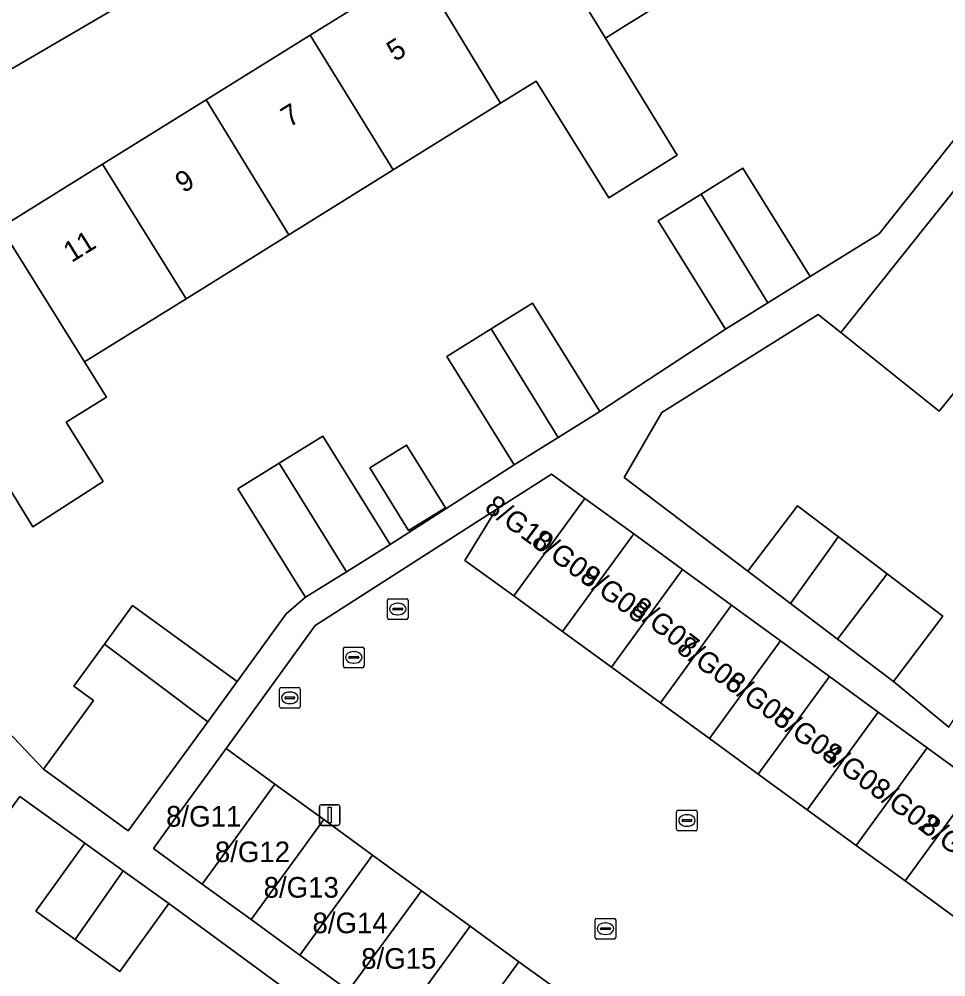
# Model space of a CAD drawing. Extents: x 159674 to 160531, y 382172 to 382904.
# Drawn here: x 160238.74 to 160283.66, y 382664.64 to 382711.06 of the extents above; entities that cross this region are included whole.
import ezdxf

# ---------------------------------------------------------------- set-up
doc = ezdxf.new("R2010")
doc.units = 0
for name, color, linetype in [('IMGEO_Erf', 7, 'Continuous'), ('IMGEO_Kolk', 7, 'Continuous'), ('IMGEO_Lichtmast', 7, 'Continuous'), ('IMGEO_Pand', 7, 'Continuous'), ('IMGEO_Pand_nummerreeks', 7, 'Continuous'), ('IMGEO_Rijbaan_lokaal_open', 7, 'Continuous'), ('IMGEO_Rioolput', 7, 'Continuous'), ('IMGEO_Voetpad_open', 7, 'Continuous')]:
    doc.layers.add(name, color=color, linetype=linetype)

msp = doc.modelspace()

# ---------------------------------------------------------------- linework, layer by layer
at = {"layer": 'IMGEO_Erf'}
for points in [[(160263.63, 382697.299), (160266.891, 382692.05), (160272.972, 382696.028), (160269.707, 382701.284), (160271.793, 382702.58), (160273.825, 382703.842), (160277.09, 382698.586), (160280.422, 382700.656), (160288.011, 382710.171), (160267.842, 382726.279), (160267.481, 382726.359), (160260.898, 382722.304), (160245.542, 382712.846), (160232.632, 382705.313), (160223.268, 382700.381)], [(160237.854, 382700.968), (160242.783, 382704.03), (160247.804, 382707.149), (160252.846, 382710.282), (160258.092, 382713.54), (160263.149, 382716.682), (160268.281, 382719.87), (160272.331, 382713.35), (160268.084, 382710.712), (160267.16, 382710.138), (160270.635, 382704.465), (160267.317, 382702.401), (160263.802, 382708.052), (160262.075, 382706.979), (160256.874, 382703.748), (160251.809, 382700.602), (160246.834, 382697.511), (160241.905, 382694.449), (160242.971, 382692.734), (160241.022, 382691.523), (160242.806, 382688.652), (160239.401, 382686.46), (160237.89, 382688.94)], [(160220.353, 382695.284), (160229.296, 382685.901), (160239.918, 382674.707), (160242.34, 382678.033), (160241.388, 382678.726), (160242.872, 382680.764), (160244.241, 382682.644), (160249.304, 382678.957), (160251.69, 382682.234), (160252.614, 382683.042), (160252.357, 382683.456), (160249.341, 382688.292), (160251.34, 382689.533), (160253.463, 382690.852), (160256.728, 382685.597), (160262.73, 382689.465), (160259.469, 382694.714), (160261.62, 382696.05), (160263.63, 382697.299)], [(160251.52, 382664.137), (160245.989, 382668.201), (160243.616, 382664.9), (160241.448, 382666.459), (160239.549, 382667.824), (160241.922, 382671.125), (160238.771, 382673.39), (160232.124, 382664.262)]]:
    msp.add_lwpolyline(points, dxfattribs=at)
for points in [[(160295.415, 382687.898), (160290.71, 382691.655), (160286.035, 382695.389), (160283.335, 382692.062), (160278.571, 382695.866), (160277.467, 382696.748), (160269.889, 382691.992), (160268.069, 382688.847), (160274.061, 382684.308), (160276.462, 382687.478), (160278.456, 382685.968), (160280.815, 382684.181), (160283.52, 382682.132), (160281.118, 382678.962), (160283.801, 382676.741), (160286.155, 382680.338), (160288.175, 382678.867), (160290.216, 382677.381), (160289.667, 382676.626), (160293.592, 382673.768), (160299.053, 382681.203), (160298.359, 382681.809), (160293.534, 382685.524)], [(160259.398, 382687.377), (160257.617, 382686.27), (160255.73, 382689.308), (160257.511, 382690.415)]]:
    msp.add_lwpolyline(points, close=True, dxfattribs=at)
at = {"layer": 'IMGEO_Kolk'}
for p, q in [((160256.591, 382682.042), (160256.591, 382682.894)), ((160256.666, 382682.968), (160257.518, 382682.968)), ((160257.079, 382682.748), (160257.104, 382682.748)), ((160257.592, 382682.894), (160257.592, 382682.042)), ((160256.85, 382682.462), (160256.85, 382682.474)), ((160257.288, 382682.425), (160256.89, 382682.425)), ((160256.893, 382682.511), (160257.291, 382682.511)), ((160257.102, 382682.188), (160257.077, 382682.188)), ((160257.334, 382682.474), (160257.334, 382682.462)), ((160257.518, 382681.968), (160256.666, 382681.968)), ((160251.361, 382677.74), (160251.361, 382678.592)), ((160251.436, 382678.666), (160252.288, 382678.666)), ((160252.362, 382678.592), (160252.362, 382677.74)), ((160251.62, 382678.16), (160251.62, 382678.172)), ((160252.058, 382678.123), (160251.66, 382678.123)), ((160251.663, 382678.209), (160252.061, 382678.209)), ((160251.849, 382678.446), (160251.874, 382678.446)), ((160252.104, 382678.172), (160252.104, 382678.16)), ((160252.288, 382677.666), (160251.436, 382677.666)), ((160251.872, 382677.886), (160251.847, 382677.886)), ((160270.611, 382671.796), (160270.611, 382672.648)), ((160270.686, 382672.722), (160271.538, 382672.722)), ((160271.099, 382672.502), (160271.124, 382672.502)), ((160271.612, 382672.648), (160271.612, 382671.796)), ((160270.87, 382672.216), (160270.87, 382672.228)), ((160271.308, 382672.179), (160270.91, 382672.179)), ((160270.913, 382672.265), (160271.311, 382672.265)), ((160271.354, 382672.228), (160271.354, 382672.216)), ((160271.538, 382671.722), (160270.686, 382671.722)), ((160271.122, 382671.942), (160271.097, 382671.942)), ((160266.659, 382666.55), (160266.659, 382667.402)), ((160266.734, 382667.476), (160267.586, 382667.476)), ((160267.66, 382667.402), (160267.66, 382666.55)), ((160266.918, 382666.97), (160266.918, 382666.982)), ((160267.356, 382666.933), (160266.958, 382666.933)), ((160266.961, 382667.019), (160267.359, 382667.019)), ((160267.147, 382667.256), (160267.172, 382667.256)), ((160267.402, 382666.982), (160267.402, 382666.97)), ((160267.586, 382666.476), (160266.734, 382666.476)), ((160267.17, 382666.696), (160267.145, 382666.696))]:
    msp.add_line(p, q, dxfattribs=at)
for points in [[(160256.591, 382682.042), (160256.591, 382682.894)], [(160256.666, 382682.968), (160257.518, 382682.968)], [(160257.592, 382682.894), (160257.592, 382682.042)], [(160257.518, 382681.968), (160256.666, 382681.968)], [(160251.361, 382677.74), (160251.361, 382678.592)], [(160251.436, 382678.666), (160252.288, 382678.666)], [(160252.362, 382678.592), (160252.362, 382677.74)], [(160252.288, 382677.666), (160251.436, 382677.666)], [(160270.611, 382671.796), (160270.611, 382672.648)], [(160270.686, 382672.722), (160271.538, 382672.722)], [(160271.612, 382672.648), (160271.612, 382671.796)], [(160271.538, 382671.722), (160270.686, 382671.722)], [(160266.659, 382666.55), (160266.659, 382667.402)], [(160266.734, 382667.476), (160267.586, 382667.476)], [(160267.66, 382667.402), (160267.66, 382666.55)], [(160267.586, 382666.476), (160266.734, 382666.476)]]:
    msp.add_lwpolyline(points, dxfattribs=at)
for centre, radius, start, end in [((160256.668, 382682.892), 0.0765, 91.552, 178.448), ((160256.668, 382682.892), 0.0765, 91.552, 178.448), ((160257.516, 382682.892), 0.0765, 1.552, 88.448), ((160257.516, 382682.892), 0.0765, 1.552, 88.448), ((160256.89, 382682.471), 0.0403, 85.8775, 175.7526), ((160256.887, 382682.461), 0.0366, 178.938, 274.7102), ((160257.291, 382682.468), 0.043, 264.8664, 352.4533), ((160257.295, 382682.473), 0.0386, 1.7309, 96.639), ((160256.668, 382682.044), 0.0765, 181.552, 268.448), ((160256.668, 382682.044), 0.0765, 181.552, 268.448), ((160257.516, 382682.044), 0.0765, 271.552, 358.448), ((160257.516, 382682.044), 0.0765, 271.552, 358.448), ((160251.438, 382678.59), 0.0765, 91.552, 178.448), ((160251.438, 382678.59), 0.0765, 91.552, 178.448), ((160252.286, 382678.59), 0.0765, 1.552, 88.448), ((160252.286, 382678.59), 0.0765, 1.552, 88.448), ((160251.66, 382678.169), 0.0403, 85.8775, 175.7526), ((160251.657, 382678.159), 0.0366, 178.938, 274.7102), ((160252.061, 382678.166), 0.043, 264.8664, 352.4533), ((160252.065, 382678.171), 0.0386, 1.7309, 96.639), ((160251.438, 382677.742), 0.0765, 181.552, 268.448), ((160251.438, 382677.742), 0.0765, 181.552, 268.448), ((160252.286, 382677.742), 0.0765, 271.552, 358.448), ((160252.286, 382677.742), 0.0765, 271.552, 358.448), ((160270.688, 382672.646), 0.0765, 91.552, 178.448), ((160270.688, 382672.646), 0.0765, 91.552, 178.448), ((160271.536, 382672.646), 0.0765, 1.552, 88.448), ((160271.536, 382672.646), 0.0765, 1.552, 88.448), ((160270.91, 382672.225), 0.0403, 85.8775, 175.7526), ((160270.907, 382672.215), 0.0366, 178.938, 274.7102), ((160271.311, 382672.222), 0.043, 264.8664, 352.4533), ((160271.315, 382672.227), 0.0386, 1.7309, 96.639), ((160270.688, 382671.798), 0.0765, 181.552, 268.448), ((160270.688, 382671.798), 0.0765, 181.552, 268.448), ((160271.536, 382671.798), 0.0765, 271.552, 358.448), ((160271.536, 382671.798), 0.0765, 271.552, 358.448), ((160266.736, 382667.4), 0.0765, 91.552, 178.448), ((160266.736, 382667.4), 0.0765, 91.552, 178.448), ((160267.584, 382667.4), 0.0765, 1.552, 88.448), ((160267.584, 382667.4), 0.0765, 1.552, 88.448), ((160266.958, 382666.979), 0.0403, 85.8775, 175.7526), ((160266.955, 382666.969), 0.0366, 178.938, 274.7102), ((160267.359, 382666.976), 0.043, 264.8664, 352.4533), ((160267.363, 382666.981), 0.0386, 1.7309, 96.639), ((160266.736, 382666.552), 0.0765, 181.552, 268.448), ((160266.736, 382666.552), 0.0765, 181.552, 268.448), ((160267.584, 382666.552), 0.0765, 271.552, 358.448), ((160267.584, 382666.552), 0.0765, 271.552, 358.448)]:
    msp.add_arc(centre, radius, start, end, dxfattribs=at)
for centre, major_axis, ratio, start_param, end_param in [((160257.078, 382682.468), (-0.387, 0.002), 0.722429, 4.712389, 7.853982), ((160257.103, 382682.468), (-0.39, 0.002), 0.717154, 1.570796, 4.712389), ((160251.848, 382678.166), (-0.387, 0.002), 0.722429, 4.712389, 7.853982), ((160251.873, 382678.166), (-0.39, 0.002), 0.717154, 1.570796, 4.712389), ((160271.098, 382672.222), (-0.387, 0.002), 0.722429, 4.712389, 7.853982), ((160271.123, 382672.222), (-0.39, 0.002), 0.717154, 1.570796, 4.712389), ((160267.146, 382666.976), (-0.387, 0.002), 0.722429, 4.712389, 7.853982), ((160267.171, 382666.976), (-0.39, 0.002), 0.717154, 1.570796, 4.712389)]:
    msp.add_ellipse(centre, major_axis=major_axis, ratio=ratio, start_param=start_param, end_param=end_param, dxfattribs=at)
at = {"layer": 'IMGEO_Lichtmast'}
for p, q in [((160253.296, 382672.087), (160253.296, 382672.887)), ((160253.296, 382672.887), (160253.296, 382672.087)), ((160253.396, 382672.987), (160254.186, 382672.987)), ((160254.186, 382672.987), (160253.396, 382672.987)), ((160254.286, 382672.887), (160254.286, 382672.087)), ((160254.286, 382672.087), (160254.286, 382672.887)), ((160254.186, 382671.987), (160253.396, 382671.987)), ((160253.396, 382671.987), (160254.186, 382671.987))]:
    msp.add_line(p, q, dxfattribs=at)
msp.add_lwpolyline([(160253.716, 382672.862), (160253.866, 382672.862), (160253.866, 382672.112), (160253.716, 382672.112), (160253.716, 382672.862)], dxfattribs=at)
for centre, start, end in [((160253.396, 382672.887), 90, 180), ((160253.396, 382672.887), 90, 180), ((160254.186, 382672.887), 0, 90), ((160254.186, 382672.887), 360, 90), ((160253.396, 382672.087), 180, 270), ((160253.396, 382672.087), 180, 270), ((160254.186, 382672.087), 270, 0), ((160254.186, 382672.087), 270, 0)]:
    msp.add_arc(centre, 0.1, start, end, dxfattribs=at)
at = {"layer": 'IMGEO_Pand'}
for points in [[(160263.149, 382716.682), (160267.16, 382710.138), (160268.084, 382710.712), (160272.331, 382713.35), (160268.281, 382719.87)], [(160258.092, 382713.54), (160262.075, 382706.979), (160263.802, 382708.052), (160267.317, 382702.401), (160270.635, 382704.465), (160267.16, 382710.138), (160263.149, 382716.682)], [(160258.092, 382713.54), (160252.846, 382710.282), (160256.874, 382703.748), (160262.075, 382706.979)], [(160251.809, 382700.602), (160256.874, 382703.748), (160252.846, 382710.282), (160247.804, 382707.149), (160250.763, 382702.312)], [(160246.834, 382697.511), (160251.809, 382700.602), (160250.763, 382702.312), (160247.804, 382707.149), (160242.783, 382704.03)], [(160290.913, 382701.497), (160286.123, 382705.323), (160278.571, 382695.866), (160283.335, 382692.062), (160286.035, 382695.389)], [(160246.834, 382697.511), (160242.783, 382704.03), (160237.854, 382700.968), (160241.905, 382694.449)], [(160271.793, 382702.58), (160275.026, 382697.304), (160277.09, 382698.586), (160273.825, 382703.842)], [(160271.793, 382702.58), (160269.707, 382701.284), (160272.972, 382696.028), (160275.026, 382697.304)], [(160241.905, 382694.449), (160237.854, 382700.968), (160232.565, 382697.682), (160237.89, 382688.94), (160239.401, 382686.46), (160242.806, 382688.652), (160241.022, 382691.523), (160242.971, 382692.734)], [(160264.862, 382690.79), (160266.891, 382692.05), (160263.63, 382697.299), (160261.62, 382696.05)], [(160264.862, 382690.79), (160261.62, 382696.05), (160259.469, 382694.714), (160262.73, 382689.465)], [(160251.34, 382689.533), (160254.605, 382684.278), (160256.728, 382685.597), (160253.463, 382690.852)], [(160259.398, 382687.377), (160257.511, 382690.415), (160255.73, 382689.308), (160257.617, 382686.27)], [(160251.34, 382689.533), (160249.341, 382688.292), (160252.357, 382683.456), (160252.614, 382683.042), (160254.605, 382684.278)], [(160262.712, 382683.102), (160266.158, 382687.835), (160264.543, 382689.011), (160261.864, 382687.295), (160260.341, 382684.828)], [(160265.084, 382681.375), (160268.53, 382686.108), (160266.158, 382687.835), (160262.712, 382683.102)], [(160276.132, 382682.739), (160278.073, 382685.441), (160278.412, 382685.913), (160278.456, 382685.968), (160276.462, 382687.478), (160274.061, 382684.308)], [(160267.455, 382679.648), (160270.901, 382684.382), (160268.53, 382686.108), (160265.084, 382681.375)], [(160276.132, 382682.739), (160278.413, 382681.011), (160280.815, 382684.181), (160278.456, 382685.968), (160278.412, 382685.913), (160278.073, 382685.441)], [(160269.826, 382677.922), (160273.272, 382682.655), (160270.901, 382684.382), (160267.455, 382679.648)], [(160280.815, 382684.181), (160278.413, 382681.011), (160281.118, 382678.962), (160283.52, 382682.132)], [(160247.879, 382677), (160249.304, 382678.957), (160244.241, 382682.644), (160242.872, 382680.764)], [(160269.826, 382677.922), (160272.198, 382676.196), (160275.644, 382680.929), (160273.272, 382682.655)], [(160272.198, 382676.196), (160274.569, 382674.469), (160278.015, 382679.202), (160275.644, 382680.929)], [(160247.879, 382677), (160242.872, 382680.764), (160241.388, 382678.726), (160242.34, 382678.033), (160239.918, 382674.707), (160244.03, 382671.713)], [(160276.94, 382672.742), (160280.386, 382677.475), (160278.015, 382679.202), (160274.569, 382674.469)], [(160279.311, 382671.016), (160282.757, 382675.749), (160280.386, 382677.475), (160276.94, 382672.742)], [(160251.14, 382673.984), (160248.775, 382675.706), (160245.832, 382671.665), (160245.25, 382670.865), (160247.615, 382669.143)], [(160285.129, 382674.022), (160282.757, 382675.749), (160279.311, 382671.016), (160281.683, 382669.29)], [(160251.14, 382673.984), (160247.615, 382669.143), (160249.98, 382667.421), (160253.505, 382672.262)], [(160285.129, 382674.022), (160281.683, 382669.29), (160284.054, 382667.563), (160284.95, 382668.814), (160287.49, 382672.303)], [(160252.345, 382665.699), (160255.87, 382670.54), (160253.505, 382672.262), (160249.98, 382667.421)], [(160241.448, 382666.459), (160243.786, 382669.785), (160241.922, 382671.125), (160239.549, 382667.824)], [(160252.345, 382665.699), (160254.71, 382663.977), (160258.235, 382668.818), (160255.87, 382670.54)], [(160241.448, 382666.459), (160243.616, 382664.9), (160245.989, 382668.201), (160243.786, 382669.785)], [(160260.6, 382667.096), (160258.235, 382668.818), (160254.71, 382663.977), (160257.075, 382662.255)], [(160260.6, 382667.096), (160257.075, 382662.255), (160259.44, 382660.533), (160262.965, 382665.374)], [(160261.805, 382658.811), (160265.33, 382663.652), (160262.965, 382665.374), (160259.44, 382660.533)]]:
    msp.add_lwpolyline(points, close=True, dxfattribs=at)
at = {"layer": 'IMGEO_Rijbaan_lokaal_open'}
msp.add_lwpolyline([(160284.054, 382667.563), (160281.683, 382669.29), (160279.311, 382671.016), (160276.94, 382672.742), (160274.569, 382674.469), (160272.198, 382676.196), (160269.826, 382677.922), (160267.455, 382679.648), (160265.084, 382681.375), (160262.712, 382683.102), (160260.341, 382684.828), (160261.864, 382687.295), (160253.096, 382681.676), (160248.775, 382675.706), (160251.14, 382673.984), (160253.505, 382672.262), (160255.87, 382670.54), (160258.235, 382668.818), (160260.6, 382667.096), (160262.965, 382665.374), (160265.33, 382663.652)], dxfattribs=at)
at = {"layer": 'IMGEO_Rioolput'}
for p, q in [((160254.459, 382679.701), (160254.459, 382680.553)), ((160254.534, 382680.627), (160255.386, 382680.627)), ((160254.947, 382680.407), (160254.972, 382680.407)), ((160255.46, 382680.553), (160255.46, 382679.701)), ((160254.718, 382680.121), (160254.718, 382680.133)), ((160255.156, 382680.084), (160254.758, 382680.084)), ((160254.761, 382680.17), (160255.159, 382680.17)), ((160254.97, 382679.847), (160254.945, 382679.847)), ((160255.202, 382680.133), (160255.202, 382680.121)), ((160255.386, 382679.627), (160254.534, 382679.627))]:
    msp.add_line(p, q, dxfattribs=at)
for points in [[(160254.459, 382679.701), (160254.459, 382680.553)], [(160254.534, 382680.627), (160255.386, 382680.627)], [(160255.46, 382680.553), (160255.46, 382679.701)], [(160255.386, 382679.627), (160254.534, 382679.627)]]:
    msp.add_lwpolyline(points, dxfattribs=at)
for centre, radius, start, end in [((160254.536, 382680.551), 0.0765, 91.552, 178.448), ((160254.536, 382680.551), 0.0765, 91.552, 178.448), ((160255.384, 382680.551), 0.0765, 1.552, 88.448), ((160255.384, 382680.551), 0.0765, 1.552, 88.448), ((160254.758, 382680.13), 0.0403, 85.8775, 175.7526), ((160254.755, 382680.12), 0.0366, 178.938, 274.7102), ((160255.159, 382680.127), 0.043, 264.8664, 352.4533), ((160255.163, 382680.132), 0.0386, 1.7309, 96.639), ((160254.536, 382679.703), 0.0765, 181.552, 268.448), ((160254.536, 382679.703), 0.0765, 181.552, 268.448), ((160255.384, 382679.703), 0.0765, 271.552, 358.448), ((160255.384, 382679.703), 0.0765, 271.552, 358.448)]:
    msp.add_arc(centre, radius, start, end, dxfattribs=at)
for centre, major_axis, ratio, start_param, end_param in [((160254.946, 382680.127), (-0.387, 0.002), 0.722429, 4.712389, 7.853982), ((160254.971, 382680.127), (-0.39, 0.002), 0.717154, 1.570796, 4.712389)]:
    msp.add_ellipse(centre, major_axis=major_axis, ratio=ratio, start_param=start_param, end_param=end_param, dxfattribs=at)
at = {"layer": 'IMGEO_Voetpad_open'}
for points in [[(160223.268, 382700.381), (160232.632, 382705.313), (160245.542, 382712.846), (160260.898, 382722.304), (160267.481, 382726.359), (160271.573, 382729.019)], [(160288.011, 382710.171), (160280.422, 382700.656), (160277.09, 382698.586), (160275.026, 382697.304), (160272.972, 382696.028), (160266.891, 382692.05), (160264.862, 382690.79), (160262.73, 382689.465), (160256.728, 382685.597), (160254.605, 382684.278), (160252.614, 382683.042), (160251.69, 382682.234), (160249.304, 382678.957), (160247.879, 382677), (160244.03, 382671.713), (160239.918, 382674.707)], [(160283.801, 382676.741), (160281.118, 382678.962), (160278.413, 382681.011), (160276.132, 382682.739), (160274.061, 382684.308), (160268.069, 382688.847), (160269.889, 382691.992), (160277.467, 382696.748), (160278.571, 382695.866), (160286.123, 382705.323)], [(160239.918, 382674.707), (160229.296, 382685.901), (160220.353, 382695.284)], [(160254.71, 382663.977), (160252.345, 382665.699), (160249.98, 382667.421), (160247.615, 382669.143), (160245.25, 382670.865), (160245.832, 382671.665), (160248.775, 382675.706), (160253.096, 382681.676), (160261.864, 382687.295), (160264.543, 382689.011), (160266.158, 382687.835), (160268.53, 382686.108), (160270.901, 382684.382), (160273.272, 382682.655), (160275.644, 382680.929), (160278.015, 382679.202), (160280.386, 382677.475), (160282.757, 382675.749), (160285.129, 382674.022)], [(160232.124, 382664.262), (160238.771, 382673.39), (160241.922, 382671.125), (160243.786, 382669.785), (160245.989, 382668.201), (160251.52, 382664.137)]]:
    msp.add_lwpolyline(points, dxfattribs=at)

# ---------------------------------------------------------------- texts
at = {"layer": 'IMGEO_Pand_nummerreeks'}
for s, rotation, p in [('5', 31.8493, (160256.958, 382708.975)), ('7', 31.8493, (160251.831, 382705.79)), ('9', 31.8493, (160246.703, 382702.604)), ('11', 31.8493, (160241.281, 382699.237)), ('8/G10', 323.7462, (160261.241, 382687.265)), ('8/G09', 323.7462, (160263.507, 382685.604)), ('8/G08', 323.7462, (160265.855, 382683.881)), ('8/G07', 322.125, (160268.32, 382682.358)), ('8/G06', 323.7462, (160270.54, 382680.445)), ('8/G05', 323.7462, (160272.884, 382678.727)), ('8/G04', 323.7462, (160275.228, 382677.008)), ('8/G03', 323.7462, (160277.572, 382675.289)), ('8/G02', 323.7462, (160279.91, 382673.574)), ('8/G01', 323.7462, (160282.348, 382671.786))]:
    msp.add_text(s, height=1, rotation=rotation, dxfattribs=at).set_placement(p)
for s, p in [('8/G11', (160245.862, 382671.925)), ('8/G12', (160248.227, 382670.203)), ('8/G13', (160250.592, 382668.481)), ('8/G14', (160252.957, 382666.758)), ('8/G15', (160255.322, 382665.036))]:
    msp.add_text(s, height=1, dxfattribs=at).set_placement(p)

doc.saveas('drawing.dxf')
